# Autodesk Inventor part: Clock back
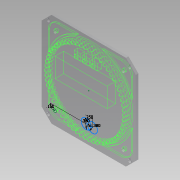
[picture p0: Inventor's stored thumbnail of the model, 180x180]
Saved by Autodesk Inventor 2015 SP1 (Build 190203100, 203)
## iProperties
Created: 2015-05
Part Number: Clock back
Material: Polycarbonate, Clear
Document SubType Name: Modeling
Designer: kazys
Density: 1.2 g/cm^3
Appearance: Clear - Yellow
Author: kazys
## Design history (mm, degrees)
sketch "Sketch1"
  geometry: L1 (-46.037, 46.038)-(46.037, 46.038); L2 (46.037, 46.038)-(46.037, -46.038); L3 (46.037, -46.038)-(-46.037, -46.038); L4 (-46.037, -46.038)-(-46.037, 46.038); L5 (42.227, 34.197)-(34.197, 42.228) reference; L6 (42.227, 34.197)-(42.227, -34.197) reference; L7 (34.197, -42.228)-(42.227, -34.197) reference; L8 (34.197, -42.228)-(-34.197, -42.228) reference; L9 (-42.227, -34.197)-(-34.197, -42.228) reference; L10 (-42.227, -34.197)-(-42.227, 34.197) reference; L11 (-34.197, 42.228)-(-42.227, 34.197) reference; L12 (-34.197, 42.228)-(34.197, 42.228) reference; L13 (-35.877, -46.799)-(35.877, -46.8) reference; L14 (46.799, -35.878)-(46.799, 35.877) reference; L15 (35.877, 46.799)-(-35.877, 46.8) reference; L16 (-46.799, 35.878)-(-46.799, -35.878) reference; C1 r 1.587 at (39.688, -39.687) reference; C2 r 1.587 at (-39.688, 39.687) reference; C3 r 1.587 at (39.687, 39.687) reference; C4 r 1.587 at (-39.688, -39.687) reference; A1 r 10.922 centre (-35.877, -35.878) between (-46.799, -35.878) and (-35.877, -46.799) reference; A2 r 10.922 centre (35.877, -35.878) between (35.877, -46.8) and (46.799, -35.878) reference; A3 r 10.922 centre (35.877, 35.878) between (46.799, 35.877) and (35.877, 46.799) reference; A4 r 10.922 centre (-35.877, 35.878) between (-35.877, 46.8) and (-46.799, 35.878) reference; 3 further points
  constraints: 8 end point, 2 midpoint, 2 parallel, 1 horizontal, 1 horizontal alignment, 1 perpendicular, 1 vertical alignment
  dimensions: "d2" = 0.762 distance between parallel lines of L15 L1; "d3" = 0.762 distance between parallel lines of L16 L4
extrude "Extrusion1" new body sketch "Sketch1" distance "d4" = 2.5; taper "d5" = 0 deg
chamfer "Chamfer1" distance "d6" = 9.652; stored, may be unused: second distance "d7" = 3.175, angle "d8" = 45 deg
sketch "Sketch2"
  geometry: L1 (46.037, -36.385)-(36.385, -46.038) reference; L2 (46.037, -36.385)-(46.037, 36.386) reference; L3 (36.385, 46.038)-(46.037, 36.386) reference; L4 (36.385, 46.038)-(-36.385, 46.038) reference; L5 (-46.037, 36.385)-(-36.385, 46.038) reference; L6 (-46.037, 36.385)-(-46.037, -36.386) reference; L7 (-36.385, -46.038)-(-46.037, -36.386) reference; L8 (-36.385, -46.038)-(36.385, -46.038) reference; C1 r 1.587 at (-39.688, -39.687) reference; C2 r 1.587 at (39.687, 39.687) reference; C3 r 1.587 at (-39.688, 39.687) reference; C4 r 1.587 at (39.688, -39.687) reference; C5 r 1.587 at (-33.338, 33.338) reference; C6 r 1.587 at (33.337, 33.338) reference; C7 r 1.587 at (33.337, -33.338) reference; C8 r 1.587 at (-33.338, -33.338) reference; 1 further point
extrude "Extrusion2" cut sketch "Sketch2" stored distance "d9" = 2.5; taper "d10" = 0 deg
sketch "Sketch4"
  geometry: L1 (-2.35, -29.274)-(3.873, -29.274); L2 (-2.35, -34.1)-(3.873, -34.099); L3 (3.873, -24.447)-(-2.35, -24.448); C1 r 1.587 at (-33.338, -33.338) reference; C2 r 1.587 at (33.337, -33.338) reference; A1 r 4.826 centre (-2.35, -29.274) between (-2.35, -24.448) and (-2.35, -34.1); A2 r 4.826 centre (3.873, -29.274) between (3.873, -34.099) and (3.873, -24.447); 2 further points
  constraints: 8 end point, 4 point on circle, 4 tangent, 2 centre point, 1 horizontal, 1 midpoint, 1 parallel
  dimensions: "d16" = 9.652 diameter of A2; "d18" = 15.875 dimension on A2 A1; "d19" = 30.988 horizontal distance of L1.start C1.centre; "d20" = 29.464 horizontal distance of L1.end C2.centre (derived); "d21" = 4.064 vertical distance of L1.start C1.centre
extrude "Extrusion3" cut sketch "Sketch4" stored distance "d22" = 25.4; taper "d23" = 0 deg
body "Solid1"
node "Reference1"
node "Projected Loop1"
node "Reference2"
node "Reference3"
node "Reference4"
node "Reference5"
